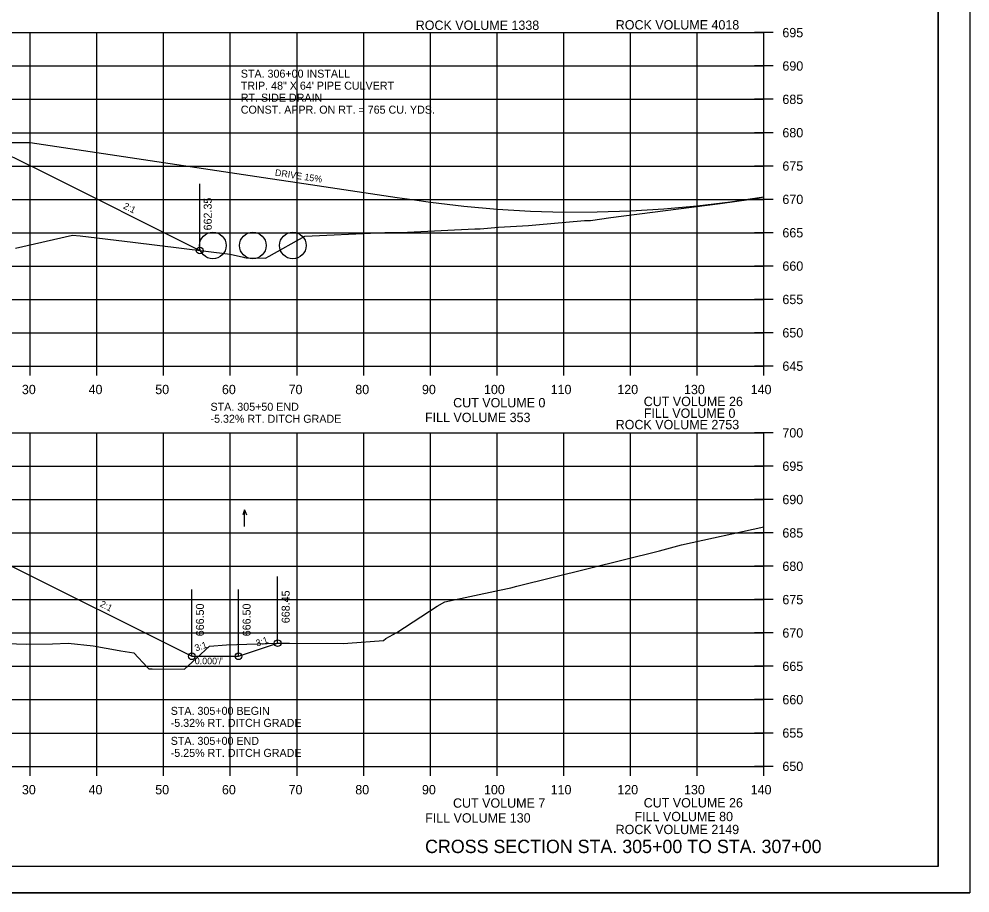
# Model space of a CAD drawing. Extents: x 1370515 to 1370849, y 383299 to 386073.
# Drawn here: x 1370706.1 to 1370848.7, y 384152.8 to 384283.8 of the extents above; entities that cross this region are included whole.
import ezdxf

# ---------------------------------------------------------------- set-up
doc = ezdxf.new("R2010")
doc.units = 0
for name, color, linetype in [('R_Axis', 7, 'Continuous'), ('R_Axis Annot', 7, 'Continuous'), ('R_Border', 7, 'Continuous'), ('R_Draft', 7, 'Continuous'), ('R_Drive', 7, 'Continuous'), ('R_Exist Surface', 7, 'Continuous'), ('R_Fin Surface', 7, 'Continuous'), ('R_Grid', 7, 'Continuous'), ('R_No Plot', 7, 'Continuous'), ('R_Water', 7, 'Continuous'), ('R_Water Annot', 7, 'Continuous'), ('R_Xsect Elev', 7, 'Continuous'), ('R_Xsect Slope', 7, 'Continuous')]:
    doc.layers.add(name, color=color, linetype=linetype)

msp = doc.modelspace()

# ---------------------------------------------------------------- linework, layer by layer
at = {"layer": 'R_Axis'}
for p, q in [((1370819.2, 384281.76), (1370816.4, 384281.76)), ((1370817.8, 384231.76), (1370817.8, 384281.76)), ((1370819.2, 384276.76), (1370816.4, 384276.76)), ((1370819.2, 384271.76), (1370816.4, 384271.76)), ((1370819.2, 384266.76), (1370816.4, 384266.76)), ((1370819.2, 384261.76), (1370816.4, 384261.76)), ((1370819.2, 384256.76), (1370816.4, 384256.76)), ((1370819.2, 384251.76), (1370816.4, 384251.76)), ((1370819.2, 384246.76), (1370816.4, 384246.76)), ((1370819.2, 384241.76), (1370816.4, 384241.76)), ((1370819.2, 384236.76), (1370816.4, 384236.76)), ((1370707.8, 384230.36), (1370707.8, 384233.16)), ((1370717.8, 384230.36), (1370717.8, 384233.16)), ((1370727.8, 384230.36), (1370727.8, 384233.16)), ((1370737.8, 384230.36), (1370737.8, 384233.16)), ((1370747.8, 384230.36), (1370747.8, 384233.16)), ((1370757.8, 384230.36), (1370757.8, 384233.16)), ((1370767.8, 384230.36), (1370767.8, 384233.16)), ((1370777.8, 384230.36), (1370777.8, 384233.16)), ((1370787.8, 384230.36), (1370787.8, 384233.16)), ((1370797.8, 384230.36), (1370797.8, 384233.16)), ((1370807.8, 384230.36), (1370807.8, 384233.16)), ((1370817.8, 384230.36), (1370817.8, 384233.16)), ((1370537.8, 384231.76), (1370817.8, 384231.76)), ((1370819.2, 384231.76), (1370816.4, 384231.76)), ((1370819.2, 384221.76), (1370816.4, 384221.76)), ((1370817.8, 384171.76), (1370817.8, 384221.76)), ((1370819.2, 384216.76), (1370816.4, 384216.76)), ((1370819.2, 384211.76), (1370816.4, 384211.76)), ((1370819.2, 384206.76), (1370816.4, 384206.76)), ((1370819.2, 384201.76), (1370816.4, 384201.76)), ((1370819.2, 384196.76), (1370816.4, 384196.76)), ((1370819.2, 384191.76), (1370816.4, 384191.76)), ((1370819.2, 384186.76), (1370816.4, 384186.76)), ((1370819.2, 384181.76), (1370816.4, 384181.76)), ((1370819.2, 384176.76), (1370816.4, 384176.76)), ((1370707.8, 384170.36), (1370707.8, 384173.16)), ((1370717.8, 384170.36), (1370717.8, 384173.16)), ((1370727.8, 384170.36), (1370727.8, 384173.16)), ((1370737.8, 384170.36), (1370737.8, 384173.16)), ((1370747.8, 384170.36), (1370747.8, 384173.16)), ((1370757.8, 384170.36), (1370757.8, 384173.16)), ((1370767.8, 384170.36), (1370767.8, 384173.16)), ((1370777.8, 384170.36), (1370777.8, 384173.16)), ((1370787.8, 384170.36), (1370787.8, 384173.16)), ((1370797.8, 384170.36), (1370797.8, 384173.16)), ((1370807.8, 384170.36), (1370807.8, 384173.16)), ((1370817.8, 384170.36), (1370817.8, 384173.16)), ((1370537.8, 384171.76), (1370817.8, 384171.76)), ((1370819.2, 384171.76), (1370816.4, 384171.76))]:
    msp.add_line(p, q, dxfattribs=at)
at = {"layer": 'R_Border'}
for q in [(1370843.98, 384362.22), (1370527.8, 384156.76)]:
    msp.add_line((1370843.98, 384156.76), q, dxfattribs=at)
at = {"layer": 'R_Exist Surface'}
for points in [[(1370705.59, 384249.44), (1370714.14, 384251.41), (1370715.26, 384251.31), (1370723.19, 384250.35), (1370737.76, 384248.55), (1370739.8, 384248.08), (1370739.94, 384248.03), (1370740.16, 384248.02), (1370743.1, 384247.94), (1370743.64, 384248.27), (1370748.96, 384251.26), (1370759.91, 384251.73), (1370760.99, 384251.78), (1370761.22, 384251.8), (1370762, 384251.8), (1370764.36, 384251.83), (1370774.46, 384252.34), (1370775.26, 384252.37), (1370778.04, 384252.6), (1370782.53, 384252.83), (1370783.6, 384252.93), (1370790.9, 384253.6), (1370791.82, 384253.6), (1370794.86, 384254.03), (1370811.29, 384256.12), (1370815.9, 384256.81), (1370817.8, 384257.13)], [(1370701.13, 384190.26), (1370707.22, 384190.06), (1370711.11, 384190.13), (1370713.5, 384190.25), (1370717.22, 384189.82), (1370721.13, 384189.12), (1370721.38, 384189.06), (1370723.35, 384188.8), (1370725.36, 384186.59), (1370725.57, 384186.38), (1370726.07, 384186.37), (1370730.92, 384186.34), (1370732.09, 384187.39), (1370734.66, 384189.78), (1370737.22, 384189.97), (1370744.87, 384190.22), (1370746.69, 384190.21), (1370754.8, 384190.19), (1370755.44, 384190.23), (1370760.78, 384190.65), (1370761.12, 384190.95), (1370762.79, 384191.81), (1370768.83, 384195.8), (1370769.99, 384196.45), (1370778.19, 384198.17), (1370779.85, 384198.53), (1370780.79, 384198.76), (1370802.15, 384204.07), (1370805.48, 384204.97), (1370817.8, 384207.68)]]:
    msp.add_lwpolyline(points, dxfattribs=at)
at = {"layer": 'R_Fin Surface'}
for points in [[(1370633.25, 384259.6), (1370651.8, 384265.78), (1370657.8, 384267.28), (1370665.8, 384266.89), (1370677.8, 384266.3), (1370689.8, 384265.71), (1370697.8, 384265.31), (1370703.8, 384263.81), (1370709.47, 384260.98), (1370733.21, 384249.11)], [(1370702.8, 384265.31), (1370707.8, 384265.31), (1370712.8, 384264.56), (1370717.8, 384263.81), (1370722.8, 384263.06), (1370727.8, 384262.31), (1370732.8, 384261.56), (1370737.8, 384260.81), (1370742.8, 384260.06), (1370747.8, 384259.31), (1370752.8, 384258.56), (1370757.8, 384257.81), (1370762.8, 384257.06), (1370765.07, 384256.72), (1370767.8, 384256.34), (1370772.8, 384255.74), (1370777.8, 384255.3), (1370782.8, 384255.01), (1370787.8, 384254.86), (1370792.8, 384254.87), (1370797.8, 384255.03), (1370802.8, 384255.34), (1370807.8, 384255.79), (1370812.8, 384256.4), (1370815.07, 384256.72), (1370817.8, 384257.13)], [(1370642.66, 384199.86), (1370651.8, 384202.91), (1370657.8, 384204.41), (1370665.8, 384204.42), (1370677.8, 384204.44), (1370689.8, 384204.2), (1370697.8, 384203.88), (1370703.09, 384202.56), (1370703.8, 384202.38), (1370732.04, 384188.26), (1370739.04, 384188.26), (1370744.9, 384190.22)]]:
    msp.add_lwpolyline(points, dxfattribs=at)
at = {"layer": 'R_Grid'}
for p, q in [((1370537.8, 384281.76), (1370817.8, 384281.76)), ((1370707.8, 384231.76), (1370707.8, 384281.76)), ((1370717.8, 384231.76), (1370717.8, 384281.76)), ((1370727.8, 384231.76), (1370727.8, 384281.76)), ((1370737.8, 384231.76), (1370737.8, 384281.76)), ((1370747.8, 384231.76), (1370747.8, 384281.76)), ((1370757.8, 384231.76), (1370757.8, 384281.76)), ((1370767.8, 384231.76), (1370767.8, 384281.76)), ((1370777.8, 384231.76), (1370777.8, 384281.76)), ((1370787.8, 384231.76), (1370787.8, 384281.76)), ((1370797.8, 384231.76), (1370797.8, 384281.76)), ((1370807.8, 384231.76), (1370807.8, 384281.76)), ((1370817.8, 384231.76), (1370817.8, 384281.76)), ((1370537.8, 384276.76), (1370817.8, 384276.76)), ((1370537.8, 384271.76), (1370817.8, 384271.76)), ((1370537.8, 384266.76), (1370817.8, 384266.76)), ((1370537.8, 384261.76), (1370817.8, 384261.76)), ((1370537.8, 384256.76), (1370817.8, 384256.76)), ((1370537.8, 384251.76), (1370817.8, 384251.76)), ((1370537.8, 384246.76), (1370817.8, 384246.76)), ((1370537.8, 384241.76), (1370817.8, 384241.76)), ((1370537.8, 384236.76), (1370817.8, 384236.76)), ((1370537.8, 384231.76), (1370817.8, 384231.76)), ((1370537.8, 384221.76), (1370817.8, 384221.76)), ((1370707.8, 384171.76), (1370707.8, 384221.76)), ((1370717.8, 384171.76), (1370717.8, 384221.76)), ((1370727.8, 384171.76), (1370727.8, 384221.76)), ((1370737.8, 384171.76), (1370737.8, 384221.76)), ((1370747.8, 384171.76), (1370747.8, 384221.76)), ((1370757.8, 384171.76), (1370757.8, 384221.76)), ((1370767.8, 384171.76), (1370767.8, 384221.76)), ((1370777.8, 384171.76), (1370777.8, 384221.76)), ((1370787.8, 384171.76), (1370787.8, 384221.76)), ((1370797.8, 384171.76), (1370797.8, 384221.76)), ((1370807.8, 384171.76), (1370807.8, 384221.76)), ((1370817.8, 384171.76), (1370817.8, 384221.76)), ((1370537.8, 384216.76), (1370817.8, 384216.76)), ((1370537.8, 384211.76), (1370817.8, 384211.76)), ((1370537.8, 384206.76), (1370817.8, 384206.76)), ((1370537.8, 384201.76), (1370817.8, 384201.76)), ((1370537.8, 384196.76), (1370817.8, 384196.76)), ((1370537.8, 384191.76), (1370817.8, 384191.76)), ((1370537.8, 384186.76), (1370817.8, 384186.76)), ((1370537.8, 384181.76), (1370817.8, 384181.76)), ((1370537.8, 384176.76), (1370817.8, 384176.76)), ((1370537.8, 384171.76), (1370817.8, 384171.76))]:
    msp.add_line(p, q, dxfattribs=at)
at = {"layer": 'R_No Plot'}
msp.add_line((1370515.4, 384152.78), (1370848.73, 384152.78), dxfattribs=at)
for points in [[(1370515.39, 384366.12), (1370848.73, 384366.12), (1370848.73, 384152.78), (1370515.39, 384152.78)], [(1370761.72, 384362.22), (1370761.72, 384352.34), (1370797.45, 384352.34), (1370797.45, 384349.42), (1370820.65, 384349.42), (1370820.65, 384326.21), (1370843.98, 384326.21), (1370843.98, 384156.76), (1370527.8, 384156.76), (1370527.8, 384362.22)]]:
    msp.add_lwpolyline(points, close=True, dxfattribs=at)
for centre in [(1370733.21, 384249.11), (1370744.9, 384190.22), (1370732.04, 384188.26), (1370732.04, 384188.26), (1370739.04, 384188.26)]:
    msp.add_circle(centre, 0.5, dxfattribs=at)
at = {"layer": 'R_Water'}
for centre in [(1370735.17, 384249.85), (1370741.17, 384249.85), (1370747.17, 384249.85)]:
    msp.add_circle(centre, 2, dxfattribs=at)
at = {"layer": 'R_Water Annot'}
for p, q in [((1370739.94, 384210.24), (1370739.66, 384209.47)), ((1370739.94, 384207.72), (1370739.94, 384210.24)), ((1370739.94, 384210.24), (1370740.22, 384209.47))]:
    msp.add_line(p, q, dxfattribs=at)
at = {"layer": 'R_Xsect Elev'}
for p, q in [((1370733.21, 384249.11), (1370733.21, 384259.11)), ((1370744.9, 384190.22), (1370744.9, 384200.22)), ((1370732.04, 384188.26), (1370732.04, 384198.26)), ((1370739.04, 384188.26), (1370739.04, 384198.26))]:
    msp.add_line(p, q, dxfattribs=at)

# ---------------------------------------------------------------- texts
at = {"layer": 'R_Axis Annot'}
for s, p in [('ROCK VOLUME 1338', (1370765.61, 384282.17)), ('ROCK VOLUME 4018', (1370795.61, 384282.23)), ('695', (1370820.6, 384281.06)), ('690', (1370820.6, 384276.06)), ('685', (1370820.6, 384271.06)), ('680', (1370820.6, 384266.06)), ('675', (1370820.6, 384261.06)), ('670', (1370820.6, 384256.06)), ('665', (1370820.6, 384251.06)), ('660', (1370820.6, 384246.06)), ('655', (1370820.6, 384241.06)), ('650', (1370820.6, 384236.06)), ('645', (1370820.6, 384231.06)), ('30', (1370706.54, 384227.56)), ('40', (1370716.54, 384227.56)), ('50', (1370726.54, 384227.56)), ('60', (1370736.54, 384227.56)), ('70', (1370746.54, 384227.56)), ('80', (1370756.54, 384227.56)), ('90', (1370766.54, 384227.56)), ('100', (1370775.84, 384227.56)), ('110', (1370785.84, 384227.56)), ('120', (1370795.84, 384227.56)), ('130', (1370805.84, 384227.56)), ('140', (1370815.84, 384227.56)), ('CUT VOLUME 0', (1370771.22, 384225.58)), ('CUT VOLUME 26', (1370799.8, 384225.77)), ('FILL VOLUME 0', (1370799.82, 384224.01)), ('FILL VOLUME 353', (1370767, 384223.37)), ('ROCK VOLUME 2753', (1370795.6, 384222.3)), ('700', (1370820.6, 384221.06)), ('695', (1370820.6, 384216.06)), ('690', (1370820.6, 384211.06)), ('685', (1370820.6, 384206.06)), ('680', (1370820.6, 384201.06)), ('675', (1370820.6, 384196.06)), ('670', (1370820.6, 384191.06)), ('665', (1370820.6, 384186.06)), ('660', (1370820.6, 384181.06)), ('655', (1370820.6, 384176.06)), ('650', (1370820.6, 384171.06)), ('30', (1370706.54, 384167.56)), ('40', (1370716.54, 384167.56)), ('50', (1370726.54, 384167.56)), ('60', (1370736.54, 384167.56)), ('70', (1370746.54, 384167.56)), ('80', (1370756.54, 384167.56)), ('90', (1370766.54, 384167.56)), ('100', (1370775.84, 384167.56)), ('110', (1370785.84, 384167.56)), ('120', (1370795.84, 384167.56)), ('130', (1370805.84, 384167.56)), ('140', (1370815.84, 384167.56)), ('CUT VOLUME 7', (1370771.2, 384165.56)), ('CUT VOLUME 26', (1370799.8, 384165.6)), ('FILL VOLUME 130', (1370767.02, 384163.33)), ('FILL VOLUME 80', (1370798.42, 384163.54)), ('ROCK VOLUME 2149', (1370795.59, 384161.6))]:
    msp.add_text(s, height=1.4, dxfattribs=at).set_placement(p)
at = {"layer": 'R_Draft'}
msp.add_text('CROSS SECTION STA. 305+00 TO STA. 307+00', height=2, dxfattribs=at).set_placement((1370767.01, 384158.76))
at = {"layer": 'R_Drive'}
for s, p in [('STA. 306+00 INSTALL', (1370739.37, 384275.01)), ('TRIP. 48" X 64\' PIPE CULVERT', (1370739.37, 384273.21)), ('RT. SIDE DRAIN', (1370739.37, 384271.41)), ('CONST. APPR. ON RT. = 765 CU. YDS.', (1370739.37, 384269.61)), ('STA. 305+50 END', (1370734.83, 384225.07)), ('-5.32% RT. DITCH GRADE', (1370734.83, 384223.27)), ('STA. 305+00 BEGIN', (1370728.86, 384179.48)), ('-5.32% RT. DITCH GRADE', (1370728.86, 384177.68)), ('STA. 305+00 END', (1370728.86, 384174.98)), ('-5.25% RT. DITCH GRADE', (1370728.86, 384173.18))]:
    msp.add_text(s, height=1.2, dxfattribs=at).set_placement(p)
msp.add_text('DRIVE 15%', height=1, rotation=351.4692, dxfattribs=at).set_placement((1370744.44, 384260.32))
at = {"layer": 'R_No Plot'}
for p in [(1370783.55, 384252.88), (1370714.1, 384251.36), (1370748.92, 384251.21), (1370760.95, 384251.73), (1370764.32, 384251.78), (1370775.22, 384252.32), (1370737.71, 384248.5), (1370739.9, 384247.98), (1370743.06, 384247.89), (1370802.11, 384204.02), (1370779.8, 384198.48), (1370769.94, 384196.4), (1370762.75, 384191.76), (1370707.17, 384190.01), (1370713.46, 384190.2), (1370734.61, 384189.73), (1370744.83, 384190.17), (1370754.76, 384190.14), (1370760.74, 384190.6), (1370723.31, 384188.75), (1370725.53, 384186.33), (1370730.88, 384186.29)]:
    msp.add_text('+', height=0.1, dxfattribs=at).set_placement(p)
at = {"layer": 'R_Xsect Elev'}
for s, p in [('662.35', (1370735.01, 384252.11)), ('668.45', (1370746.7, 384193.22)), ('666.50', (1370733.84, 384191.26)), ('666.50', (1370740.84, 384191.26))]:
    msp.add_text(s, height=1.2, rotation=90, dxfattribs=at).set_placement(p)
at = {"layer": 'R_Xsect Slope'}
for s, rotation, p in [('2:1', 333.4349, (1370721.64, 384255.45)), ('2:1', 333.4349, (1370718.14, 384195.77)), ('3:1', 18.4349, (1370741.81, 384189.71)), ('3:1', 18.4349, (1370732.65, 384188.99)), ("0.000'/'", 359.5792, (1370732.46, 384187.08))]:
    msp.add_text(s, height=1, rotation=rotation, dxfattribs=at).set_placement(p)

doc.saveas('drawing.dxf')
